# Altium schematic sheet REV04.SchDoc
size A
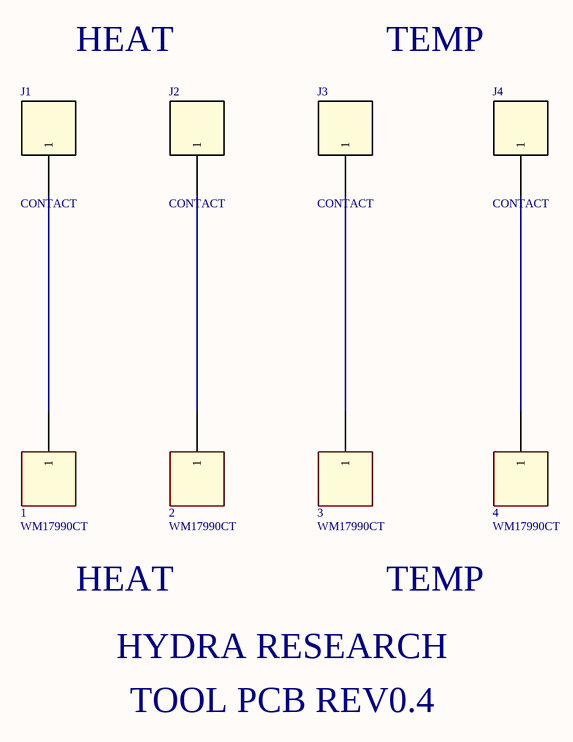
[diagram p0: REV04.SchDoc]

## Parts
1  WM17990CT  [WM17990CT-ND-l]
2  WM17990CT  [WM17990CT-ND-l]
3  WM17990CT  [WM17990CT-ND-l]
4  WM17990CT  [WM17990CT-ND-l]
J1  CONTACT  [CONTRACT PAD]
J2  CONTACT  [CONTRACT PAD]
J3  CONTACT  [CONTRACT PAD]
J4  CONTACT  [CONTRACT PAD]

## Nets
Net1_1: 1.1 J1.1
Net2_1: 2.1 J2.1
Net3_1: 3.1 J3.1
Net4_1: 4.1 J4.1

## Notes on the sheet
- HEAT
- TEMP
- HYDRA RESEARCH
- TOOL PCB REV0.4

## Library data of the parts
1-4 = WM17990CT: MPN: WM17990CT-ND
J1-J4 = CONTACT: MPN: N/C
